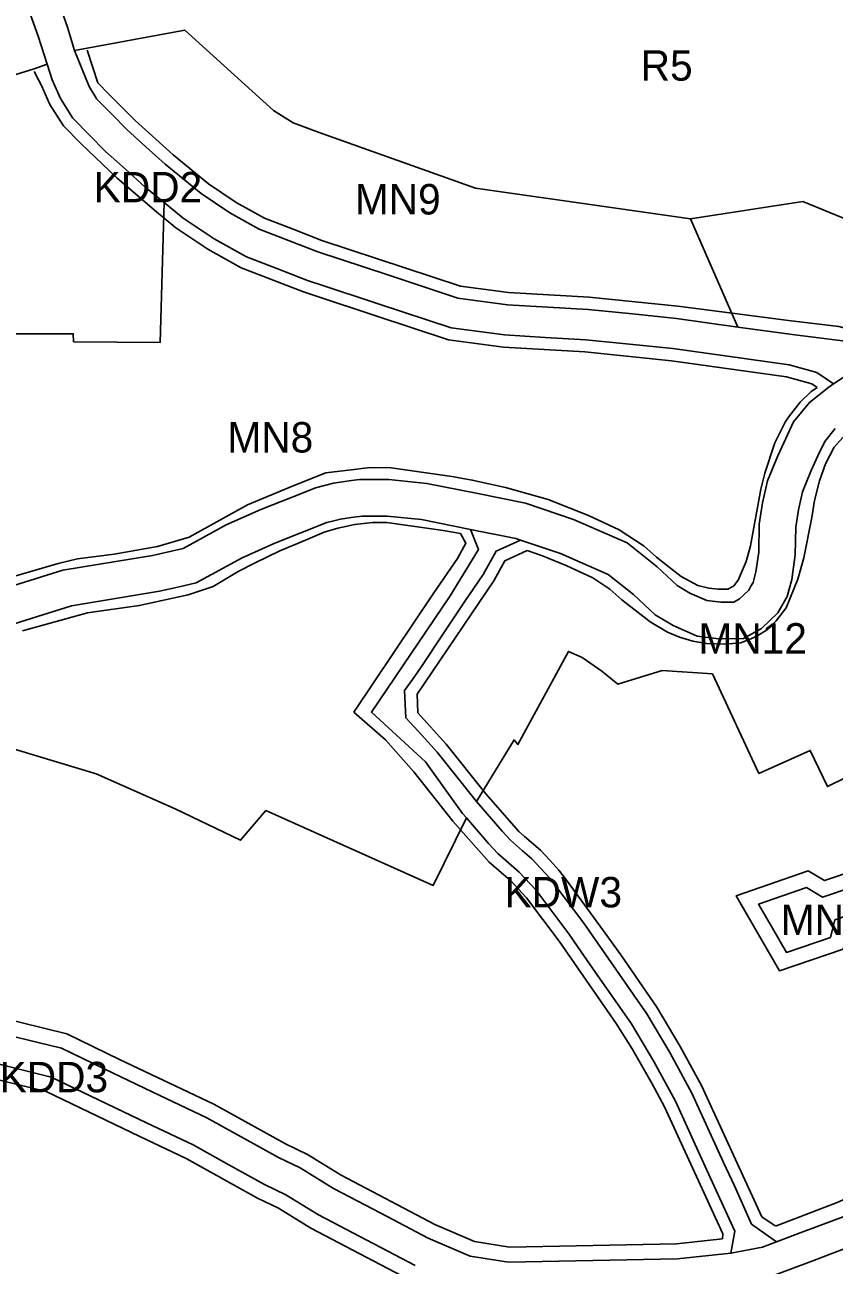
# Model space of a CAD drawing. Extents: x 7428841 to 7433518, y 5545054 to 5546840.
# Drawn here: x 7430056.9 to 7430323, y 5545838 to 5546245.5 of the extents above; entities that cross this region are included whole.
import ezdxf

# ---------------------------------------------------------------- set-up
doc = ezdxf.new("R2010")
doc.units = 0
for name, color, linetype in [('linie_rozgraniczajace', 7, 'Continuous'), ('linie_zabudowy_nieprzekraczalne', 7, 'Continuous'), ('oznaczenia_przeznaczen', 7, 'Continuous')]:
    doc.layers.add(name, color=color, linetype=linetype)

msp = doc.modelspace()

# ---------------------------------------------------------------- linework, layer by layer
at = {"layer": 'linie_rozgraniczajace'}
for points in [[(7430395.71, 5546246.95), (7430410.58, 5546240.65), (7430429.34, 5546232.43), (7430433.09, 5546231.11), (7430441.95, 5546227.01), (7430446.69, 5546224.98), (7430448.57, 5546223.18), (7430461.67, 5546201.97), (7430469.14, 5546186.36), (7430444.59, 5546177.43), (7430426.54, 5546173.53), (7430383.37, 5546165.73), (7430346.89, 5546173.43), (7430312.67, 5546187.52), (7430275.76, 5546181.81), (7430248.12, 5546185.73), (7430205.02, 5546191.83), (7430153.69, 5546210.14), (7430145.11, 5546213.38), (7430138.68, 5546217.35), (7430109.51, 5546243.79), (7430073.19, 5546237.15), (7430070.97, 5546244.81), (7430059.92, 5546275.9)], [(7430059.92, 5546275.9), (7430070.97, 5546244.81), (7430073.19, 5546237.15), (7430078, 5546225.29), (7430080.59, 5546221.14), (7430085.48, 5546216.15), (7430090.37, 5546211.16), (7430096.69, 5546205.48), (7430103.01, 5546199.79), (7430114.86, 5546190.08), (7430124.34, 5546183.79), (7430133.98, 5546178.42), (7430153.22, 5546170.96), (7430176.25, 5546163.35), (7430199.28, 5546155.75), (7430215.56, 5546153.59), (7430228.86, 5546152.81), (7430242.15, 5546152.03), (7430256.64, 5546150.56), (7430271.12, 5546149.09), (7430291.3, 5546146.25), (7430310.03, 5546143.69), (7430332.77, 5546140.78)], [(7430326.24, 5546129.84), (7430322.81, 5546127.56), (7430317.34, 5546131.29), (7430308.14, 5546133.85), (7430287.1, 5546136.77), (7430269.93, 5546139.16), (7430255.64, 5546140.61), (7430241.36, 5546142.06), (7430227.98, 5546142.85), (7430214.61, 5546143.63), (7430197.04, 5546145.96), (7430173.44, 5546153.75), (7430171.43, 5546154.41), (7430155.18, 5546159.78), (7430149.84, 5546161.54), (7430139.78, 5546165.45), (7430129.72, 5546169.35), (7430119.14, 5546175.24), (7430108.91, 5546182.03), (7430102.71, 5546187.11), (7430096.5, 5546192.2), (7430089.97, 5546198.07), (7430083.45, 5546203.94), (7430078.08, 5546209.42), (7430072.71, 5546214.9), (7430068.65, 5546221.3), (7430065.92, 5546227.47), (7430064.19, 5546232.61), (7430061.23, 5546241.83), (7430051.52, 5546269.16)], [(7430027.17, 5546220.98), (7430059.94, 5546231.03), (7430064.19, 5546232.61), (7430065.92, 5546227.47), (7430068.65, 5546221.3), (7430072.71, 5546214.9), (7430078.08, 5546209.42), (7430083.45, 5546203.94), (7430089.97, 5546198.07), (7430096.5, 5546192.2), (7430102.71, 5546187.11), (7430101.41, 5546141.18), (7430072.89, 5546141.43), (7430072.78, 5546144.05), (7430024.7, 5546144.06)], [(7430024.7, 5546144.06), (7430072.78, 5546144.05), (7430072.89, 5546141.43), (7430101.41, 5546141.18), (7430102.71, 5546187.11), (7430108.91, 5546182.03), (7430119.14, 5546175.24), (7430129.72, 5546169.35), (7430139.78, 5546165.45), (7430149.84, 5546161.54), (7430155.18, 5546159.78), (7430171.43, 5546154.41), (7430173.44, 5546153.75), (7430197.04, 5546145.96), (7430214.61, 5546143.63), (7430227.98, 5546142.85), (7430241.36, 5546142.06), (7430255.64, 5546140.61), (7430269.93, 5546139.16), (7430287.1, 5546136.77), (7430308.14, 5546133.85), (7430317.34, 5546131.29), (7430322.81, 5546127.56), (7430321.18, 5546126.47), (7430314.87, 5546121.5), (7430309.65, 5546115.1), (7430304.43, 5546103.89), (7430301.09, 5546095.75), (7430299.44, 5546088.46), (7430298.36, 5546081.51), (7430298.17, 5546072.3), (7430297.26, 5546065.78), (7430296.31, 5546062.32), (7430295.61, 5546061.08), (7430294.91, 5546059.84), (7430293.4, 5546058.41), (7430291.9, 5546056.98), (7430289.96, 5546055.89), (7430287.86, 5546055.85), (7430285.75, 5546055.81), (7430281.12, 5546056.39), (7430275.57, 5546058.82), (7430271.39, 5546061.36), (7430264.81, 5546067.43), (7430254.9, 5546075.34), (7430237.29, 5546083), (7430221.45, 5546088.34), (7430205.28, 5546091.61), (7430189.1, 5546094.88), (7430176.58, 5546096.11), (7430166.97, 5546096.15), (7430164.29, 5546095.77), (7430158.35, 5546094.94), (7430152.48, 5546093.44), (7430148.38, 5546091.82), (7430134.43, 5546086.32), (7430123.03, 5546081.21), (7430108.97, 5546073.51), (7430098.81, 5546071.19), (7430069.41, 5546066.31), (7430038.84, 5546056.81)], [(7430332.77, 5546140.78), (7430310.03, 5546143.69), (7430291.3, 5546146.25), (7430275.76, 5546181.81), (7430312.67, 5546187.52), (7430346.89, 5546173.43)], [(7430108.97, 5546073.51), (7430123.03, 5546081.21), (7430134.43, 5546086.32), (7430148.38, 5546091.82), (7430152.48, 5546093.44), (7430158.35, 5546094.94), (7430164.29, 5546095.77), (7430166.97, 5546096.15), (7430176.58, 5546096.11), (7430189.1, 5546094.88), (7430205.28, 5546091.61), (7430221.45, 5546088.34), (7430237.29, 5546083), (7430254.9, 5546075.34), (7430264.81, 5546067.43), (7430271.39, 5546061.36), (7430275.57, 5546058.82), (7430281.12, 5546056.39), (7430285.75, 5546055.81), (7430287.86, 5546055.85), (7430289.96, 5546055.89), (7430291.9, 5546056.98), (7430293.4, 5546058.41), (7430294.91, 5546059.84), (7430295.61, 5546061.08), (7430296.31, 5546062.32), (7430297.26, 5546065.78), (7430298.17, 5546072.3), (7430298.36, 5546081.51), (7430299.44, 5546088.46), (7430301.09, 5546095.75), (7430304.43, 5546103.89), (7430309.65, 5546115.1), (7430314.87, 5546121.5), (7430321.18, 5546126.47), (7430322.81, 5546127.56), (7430326.24, 5546129.84)], [(7430339.37, 5546004.41), (7430320.75, 5545995.28), (7430315.1, 5546007.13), (7430298.23, 5545999.61), (7430282.96, 5546032.29), (7430266.41, 5546033.35), (7430251.91, 5546028.91), (7430246.58, 5546033.17), (7430240.15, 5546037.7), (7430235.6, 5546039.69), (7430219.01, 5546009.07), (7430217.74, 5546010.62), (7430205.34, 5545990.31), (7430192.42, 5546006.62), (7430187.51, 5546012.03), (7430182.14, 5546017.87), (7430181.77, 5546026.82), (7430184.31, 5546030.45), (7430186.85, 5546034.08), (7430194.64, 5546045.8), (7430201.43, 5546055.91), (7430207.63, 5546064.91), (7430211.84, 5546072.56), (7430219.86, 5546076.21), (7430232.97, 5546071.79), (7430248.66, 5546064.97), (7430256.99, 5546058.32), (7430264.13, 5546051.73), (7430270.02, 5546048.14), (7430277.91, 5546044.7), (7430285.12, 5546043.8), (7430293.2, 5546043.95), (7430299.06, 5546047.24), (7430304.49, 5546052.38), (7430307.48, 5546057.72), (7430309.04, 5546063.33), (7430310.15, 5546071.35), (7430310.34, 5546080.46), (7430311.23, 5546086.21), (7430312.57, 5546092.13), (7430314, 5546095.6), (7430315.42, 5546099.08), (7430317.66, 5546103.88), (7430319.89, 5546108.68), (7430323.33, 5546112.89)], [(7430323.33, 5546112.89), (7430319.89, 5546108.68), (7430317.66, 5546103.88), (7430315.42, 5546099.08), (7430314, 5546095.6), (7430312.57, 5546092.13), (7430311.23, 5546086.21), (7430310.34, 5546080.46), (7430310.15, 5546071.35), (7430309.04, 5546063.33), (7430307.48, 5546057.72), (7430304.49, 5546052.38), (7430299.06, 5546047.24), (7430293.2, 5546043.95), (7430285.12, 5546043.8), (7430277.91, 5546044.7)], [(7430042.04, 5546045.23), (7430072.19, 5546054.6), (7430101.13, 5546059.41), (7430107.2, 5546060.8), (7430113.27, 5546062.18), (7430128.38, 5546070.45), (7430139.09, 5546075.26), (7430147.63, 5546078.63), (7430156.18, 5546082), (7430158.43, 5546082.57), (7430160.67, 5546083.15), (7430164.23, 5546083.64), (7430167.79, 5546084.14), (7430175.97, 5546084.11), (7430187.32, 5546083), (7430202.83, 5546079.86), (7430203.4, 5546079.75), (7430206.03, 5546073.17), (7430196.76, 5546057.94), (7430170.86, 5546019.72), (7430188.61, 5546003.37), (7430200.81, 5545986.39), (7430202.13, 5545985), (7430191.14, 5545962.76), (7430136.15, 5545987.37), (7430127.82, 5545977.63), (7430106.34, 5545987.97), (7430080.36, 5545999.48), (7430047.86, 5546009.17)], [(7430277.91, 5546044.7), (7430270.02, 5546048.14), (7430264.13, 5546051.73), (7430256.99, 5546058.32), (7430248.66, 5546064.97), (7430232.97, 5546071.79), (7430219.86, 5546076.21), (7430218.33, 5546076.73), (7430203.4, 5546079.75), (7430202.83, 5546079.86), (7430187.32, 5546083), (7430175.97, 5546084.11), (7430167.79, 5546084.14), (7430164.23, 5546083.64), (7430160.67, 5546083.15), (7430158.43, 5546082.57), (7430156.18, 5546082), (7430147.63, 5546078.63), (7430139.09, 5546075.26), (7430128.38, 5546070.45), (7430113.27, 5546062.18), (7430107.2, 5546060.8), (7430101.13, 5546059.41), (7430072.19, 5546054.6), (7430042.04, 5546045.23)], [(7429909.72, 5546015.03), (7429921.21, 5546015.41), (7429932.7, 5546015.79), (7429941.42, 5546017.03), (7429954.62, 5546025.5), (7429972.76, 5546035.67), (7429986.76, 5546042.68), (7429993.18, 5546045.73), (7430004.82, 5546048.78), (7430016.01, 5546051.27), (7430038.84, 5546056.81), (7430069.41, 5546066.31), (7430098.81, 5546071.19), (7430108.97, 5546073.51)], [(7430325.91, 5545853.94), (7430312.65, 5545848.93), (7430304.05, 5545845.68), (7430295.86, 5545851.52), (7430290.18, 5545864.11), (7430286.56, 5545871.78), (7430276.15, 5545894.55), (7430268.92, 5545907.86), (7430261.37, 5545920.59), (7430240.64, 5545950.36), (7430234.25, 5545958.91), (7430229.45, 5545965.17), (7430223.6, 5545971.48), (7430220.51, 5545974.18), (7430216.53, 5545977.65), (7430213.79, 5545980.56), (7430205.34, 5545990.31), (7430217.74, 5546010.62), (7430219.01, 5546009.07), (7430235.6, 5546039.69), (7430240.15, 5546037.7), (7430246.58, 5546033.17), (7430251.91, 5546028.91), (7430266.41, 5546033.35), (7430282.96, 5546032.29), (7430298.23, 5545999.61), (7430315.1, 5546007.13), (7430320.75, 5545995.28), (7430339.37, 5546004.41)], [(7430047.86, 5546009.17), (7430080.36, 5545999.48), (7430106.34, 5545987.97), (7430127.82, 5545977.63), (7430136.15, 5545987.37), (7430191.14, 5545962.76), (7430202.13, 5545985), (7430209.33, 5545976.54), (7430212.36, 5545973.32), (7430219.42, 5545967.17), (7430224.86, 5545961.3), (7430235.78, 5545946.85), (7430238.65, 5545942.71), (7430244.53, 5545934.2), (7430256.33, 5545917.33), (7430263.7, 5545904.9), (7430270.78, 5545891.89), (7430281.12, 5545869.27), (7430290.34, 5545849.18), (7430289.06, 5545841.95), (7430271.46, 5545840.08), (7430243.69, 5545839.53), (7430215.92, 5545838.98), (7430203.28, 5545841), (7430189.55, 5545846.91), (7430173.96, 5545855.07), (7430158.36, 5545863.24), (7430147.44, 5545869.97), (7430140.26, 5545873.39), (7430116.76, 5545886.43), (7430101.32, 5545893.77), (7430085.89, 5545901.11), (7430068.96, 5545909.28), (7430046.71, 5545914.73)], [(7430387.48, 5545981.93), (7430319.19, 5545958.9), (7430313.9, 5545962.12), (7430298.13, 5545956.66), (7430302.71, 5545948.72), (7430307.29, 5545940.77), (7430321.76, 5545945.71), (7430323.22, 5545951.5)], [(7430046.71, 5545914.73), (7430068.96, 5545909.28), (7430085.89, 5545901.11), (7430101.32, 5545893.77), (7430116.76, 5545886.43), (7430140.26, 5545873.39), (7430147.44, 5545869.97), (7430158.36, 5545863.24), (7430173.96, 5545855.07), (7430189.55, 5545846.91), (7430203.28, 5545841), (7430215.92, 5545838.98), (7430243.69, 5545839.53), (7430271.46, 5545840.08), (7430289.06, 5545841.95), (7430299.4, 5545843.92), (7430304.05, 5545845.68), (7430312.65, 5545848.93), (7430325.91, 5545853.94)], [(7430185.25, 5545837.88), (7430169.33, 5545846.21), (7430153.41, 5545854.54), (7430142.65, 5545861.18), (7430135.68, 5545864.5), (7430123.93, 5545871.01), (7430112.18, 5545877.53), (7430096.87, 5545884.81), (7430065.56, 5545899.82), (7430045.26, 5545904.79), (7430020.57, 5545906.02), (7429999.63, 5545902.67), (7429977.4, 5545896.7), (7429959.62, 5545892.8), (7429941.85, 5545888.91), (7429925.35, 5545885.29), (7429905.91, 5545878.08)], [(7429905.91, 5545878.08), (7429925.35, 5545885.29), (7429941.85, 5545888.91), (7429959.62, 5545892.8), (7429977.4, 5545896.7), (7429999.63, 5545902.67), (7430020.57, 5545906.02), (7430045.26, 5545904.79), (7430065.56, 5545899.82), (7430096.87, 5545884.81), (7430112.18, 5545877.53), (7430123.93, 5545871.01), (7430135.68, 5545864.5), (7430142.65, 5545861.18), (7430153.41, 5545854.54), (7430169.33, 5545846.21), (7430185.25, 5545837.88)], [(7430329.71, 5545844.69), (7430315.92, 5545839.47), (7430302.12, 5545834.26)], [(7430302.12, 5545834.26), (7430315.92, 5545839.47), (7430329.71, 5545844.69)]]:
    msp.add_lwpolyline(points, dxfattribs=at)
for points in [[(7429949.44, 5546226.76), (7429950.82, 5546228.81), (7429953.67, 5546233.22), (7429972.27, 5546244.79), (7429984.5, 5546249.98), (7430003.93, 5546257.84), (7430047.04, 5546271.67), (7430051.52, 5546269.16), (7430061.23, 5546241.83), (7430064.19, 5546232.61), (7430059.94, 5546231.03), (7430027.17, 5546220.98), (7429994.39, 5546210.92), (7429975.97, 5546200.5), (7429971.21, 5546198.5), (7429967.92, 5546207.41), (7429962.3, 5546218.77), (7429950.2, 5546223.83)], [(7430073.19, 5546237.15), (7430109.51, 5546243.79), (7430138.68, 5546217.35), (7430145.11, 5546213.38), (7430153.69, 5546210.14), (7430205.02, 5546191.83), (7430248.12, 5546185.73), (7430275.76, 5546181.81), (7430291.3, 5546146.25), (7430271.12, 5546149.09), (7430256.64, 5546150.56), (7430242.15, 5546152.03), (7430228.86, 5546152.81), (7430215.56, 5546153.59), (7430199.28, 5546155.75), (7430176.25, 5546163.35), (7430153.22, 5546170.96), (7430133.98, 5546178.42), (7430124.34, 5546183.79), (7430114.86, 5546190.08), (7430103.01, 5546199.79), (7430096.69, 5546205.48), (7430090.37, 5546211.16), (7430085.48, 5546216.15), (7430080.59, 5546221.14), (7430078, 5546225.29)], [(7430170.86, 5546019.72), (7430196.76, 5546057.94), (7430206.03, 5546073.17), (7430203.4, 5546079.75), (7430218.33, 5546076.73), (7430219.86, 5546076.21), (7430211.84, 5546072.56), (7430207.63, 5546064.91), (7430201.43, 5546055.91), (7430194.64, 5546045.8), (7430186.85, 5546034.08), (7430184.31, 5546030.45), (7430181.77, 5546026.82), (7430182.14, 5546017.87), (7430187.51, 5546012.03), (7430192.42, 5546006.62), (7430205.34, 5545990.31), (7430213.79, 5545980.56), (7430216.53, 5545977.65), (7430220.51, 5545974.18), (7430223.6, 5545971.48), (7430229.45, 5545965.17), (7430234.25, 5545958.91), (7430240.64, 5545950.36), (7430261.37, 5545920.59), (7430268.92, 5545907.86), (7430276.15, 5545894.55), (7430286.56, 5545871.78), (7430290.18, 5545864.11), (7430295.86, 5545851.52), (7430304.05, 5545845.68), (7430299.4, 5545843.92), (7430289.06, 5545841.95), (7430290.34, 5545849.18), (7430281.12, 5545869.27), (7430270.78, 5545891.89), (7430263.7, 5545904.9), (7430256.33, 5545917.33), (7430244.53, 5545934.2), (7430238.65, 5545942.71), (7430235.78, 5545946.85), (7430224.86, 5545961.3), (7430219.42, 5545967.17), (7430212.36, 5545973.32), (7430209.33, 5545976.54), (7430202.13, 5545985), (7430200.81, 5545986.39), (7430188.61, 5546003.37)], [(7430298.13, 5545956.66), (7430313.9, 5545962.12), (7430319.19, 5545958.9), (7430387.48, 5545981.93), (7430406.5, 5545994.8), (7430407.64, 5546003.07), (7430419.93, 5545987.45), (7430411.76, 5545988.73), (7430391.08, 5545974.71), (7430357.15, 5545963.1), (7430323.22, 5545951.5), (7430321.76, 5545945.71), (7430307.29, 5545940.77), (7430302.71, 5545948.72)]]:
    msp.add_lwpolyline(points, close=True, dxfattribs=at)
at = {"layer": 'linie_zabudowy_nieprzekraczalne'}
for points in [[(7430077.38, 5546237.2), (7430080.89, 5546226.48), (7430084.68, 5546222.52)], [(7430062.78, 5546224.68), (7430060, 5546230.19)], [(7430152.5, 5546156.47), (7430152.48, 5546156.47), (7430148.49, 5546157.77), (7430128.01, 5546165.72), (7430117.05, 5546171.82), (7430106.54, 5546178.81), (7430100.13, 5546184.05), (7430087.29, 5546195.1), (7430075.27, 5546206.57), (7430069.55, 5546212.4), (7430065.12, 5546219.41), (7430062.81, 5546224.61)], [(7430084.68, 5546222.52), (7430093.14, 5546214.05), (7430105.62, 5546202.82), (7430117.24, 5546193.3), (7430126.42, 5546187.21), (7430135.68, 5546182.05), (7430145.13, 5546178.39), (7430154.57, 5546174.72), (7430200.18, 5546159.67), (7430215.94, 5546157.58), (7430229.21, 5546156.8), (7430242.47, 5546156.02), (7430271.6, 5546153.06), (7430289.42, 5546150.77)], [(7430172.01, 5546149.99), (7430152.48, 5546156.49)], [(7430289.42, 5546150.77), (7430307.96, 5546148.42), (7430324.57, 5546146.39), (7430340.12, 5546142.19), (7430352.42, 5546136.67)], [(7430317.36, 5546126.43), (7430315.63, 5546127.62), (7430307.33, 5546129.93), (7430269.45, 5546135.19), (7430241.04, 5546138.08), (7430214.23, 5546139.65), (7430196.14, 5546142.05), (7430172.01, 5546149.99), (7430172.01, 5546149.99)], [(7430166.02, 5546099.5), (7430167.71, 5546099.8), (7430170.39, 5546100.08), (7430177.35, 5546099.95), (7430197.24, 5546097.16), (7430203.98, 5546095.94), (7430214.91, 5546093.56), (7430228.9, 5546089.59), (7430242.26, 5546084.35), (7430252.34, 5546079.61), (7430260.52, 5546074.21), (7430264.59, 5546070.65), (7430268.71, 5546067.35), (7430272.72, 5546064.24), (7430278.12, 5546061.3), (7430281.73, 5546060.43), (7430284.83, 5546060.14), (7430288.05, 5546060.17), (7430289.68, 5546060.95), (7430289.98, 5546061.25), (7430291.46, 5546063.1), (7430294.03, 5546069.26), (7430295.44, 5546074.37), (7430298.9, 5546092.96), (7430300.22, 5546098.19), (7430303.49, 5546108.15), (7430306.87, 5546115.03), (7430307.95, 5546116.65), (7430311.76, 5546121.54), (7430315.29, 5546124.95), (7430317.36, 5546126.43)], [(7430326.83, 5546111.07), (7430322.98, 5546106.74), (7430320.17, 5546101.29), (7430318.16, 5546095.74), (7430316.52, 5546089.2), (7430315.69, 5546083.62), (7430313.04, 5546070.47), (7430311.07, 5546063.38), (7430307.19, 5546054.03), (7430303.88, 5546049.7), (7430301.07, 5546046.88), (7430297.6, 5546044.63), (7430295.81, 5546043.88), (7430292.28, 5546042.45), (7430289.62, 5546042.24), (7430286.97, 5546042.03), (7430281.16, 5546042.28), (7430276.48, 5546043.05), (7430272.12, 5546044.3), (7430268.22, 5546045.95), (7430262.54, 5546049.36), (7430253.16, 5546056.63), (7430251.2, 5546058.39), (7430249.24, 5546060.15), (7430243.6, 5546063.85), (7430235.08, 5546067.84), (7430227.06, 5546071.09), (7430222, 5546072.86)], [(7430145.09, 5546094.11), (7430155.8, 5546098.34), (7430166.02, 5546099.5)], [(7430007.67, 5546053.2), (7430010.48, 5546052.1), (7430013.34, 5546052.73), (7430040.62, 5546060.65), (7430067.9, 5546068.57), (7430074.2, 5546070.07), (7430086.27, 5546071.65), (7430100.47, 5546074.17), (7430110.9, 5546077.25), (7430130.07, 5546087.79), (7430145.09, 5546094.11)], [(7430200.11, 5546078.43), (7430194.43, 5546079.38), (7430175.92, 5546081.98), (7430171.16, 5546082.07), (7430165.42, 5546081.35), (7430159.81, 5546080.17), (7430155.32, 5546078.82), (7430149.22, 5546076.21), (7430140.72, 5546072.73), (7430132.4, 5546068.71), (7430127.05, 5546065.93), (7430118.76, 5546060.98), (7430110.6, 5546058.28), (7430094.53, 5546054.73), (7430077.46, 5546052.35), (7430056.13, 5546046.46)], [(7430286.27, 5545846.68), (7430286.39, 5545848.37), (7430267.2, 5545890.08), (7430263.2, 5545897.65), (7430256.59, 5545909.05), (7430251.33, 5545917.42), (7430232.53, 5545944.51), (7430221.8, 5545958.72), (7430216.63, 5545964.29), (7430209.59, 5545970.44), (7430197.64, 5545983.93), (7430184.79, 5546000.15), (7430175.5, 5546010.62), (7430165.08, 5546019.75), (7430191.33, 5546058.96), (7430199.11, 5546070.17), (7430201.89, 5546075.23), (7430200.11, 5546078.43)], [(7430222, 5546072.86), (7430214.7, 5546069.47), (7430211.04, 5546062.81), (7430185.83, 5546025.64), (7430186.07, 5546019.5), (7430195.47, 5546009.2), (7430208.42, 5545992.87), (7430219.31, 5545980.53), (7430221.22, 5545978.86), (7430226.39, 5545974.36), (7430229.45, 5545971.06), (7430232.51, 5545967.76), (7430234.98, 5545964.54), (7430246.87, 5545948.3), (7430252.79, 5545940.02), (7430264.73, 5545922.76), (7430272.4, 5545909.84), (7430279.41, 5545897), (7430299.16, 5545853.91), (7430303.63, 5545850.95)], [(7430417.21, 5545982.8), (7430412.93, 5545983.48), (7430393.33, 5545970.19), (7430327.41, 5545947.65), (7430325.95, 5545941.85), (7430305.02, 5545934.71), (7430290.77, 5545959.4), (7430314.49, 5545967.61), (7430319.8, 5545964.38), (7430385.24, 5545986.45), (7430401.85, 5545997.69), (7430402.33, 5546001.78)], [(7430303.75, 5545850.89), (7430324, 5545858.57), (7430341.64, 5545866.42), (7430349.45, 5545871.39), (7430369.83, 5545886.83), (7430383.39, 5545900.53), (7430405.39, 5545922.91), (7430413.84, 5545931.6), (7430417.81, 5545936.52), (7430429.25, 5545957.56), (7430427.65, 5545966.15), (7430424.02, 5545973.98), (7430417.21, 5545982.8)], [(7429901.15, 5545892.32), (7429915.52, 5545897.85), (7429921.4, 5545899.78), (7429956.3, 5545907.43), (7429973.84, 5545911.27), (7429996.49, 5545917.36), (7430019.74, 5545921.08), (7430047.43, 5545919.7), (7430070.66, 5545914.01), (7430088.05, 5545905.62), (7430119.05, 5545890.87), (7430142.55, 5545877.84), (7430149.84, 5545874.37), (7430160.84, 5545867.58), (7430191.7, 5545851.43), (7430204.69, 5545845.83), (7430216.27, 5545843.99), (7430271.14, 5545845.08), (7430286.27, 5545846.68)], [(7430194.95, 5545828.25), (7430183.1, 5545833.36), (7430150.94, 5545850.19), (7430140.26, 5545856.78), (7430133.39, 5545860.05), (7430109.89, 5545873.08), (7430094.72, 5545880.3), (7430063.87, 5545895.09), (7430044.53, 5545899.82), (7430020.84, 5545901), (7430000.68, 5545897.77), (7429978.58, 5545891.84), (7429942.92, 5545884.02), (7429926.67, 5545880.46), (7429922.24, 5545879.01), (7429907.5, 5545873.33)]]:
    msp.add_lwpolyline(points, dxfattribs=at)

# ---------------------------------------------------------------- texts
at = {"layer": 'oznaczenia_przeznaczen'}
for s, p in [('R5', (7430259.37, 5546227.19)), ('KDD2', (7430079.53, 5546187.2)), ('MN9', (7430165.39, 5546183.23)), ('MN8', (7430123.49, 5546105.02)), ('MN12', (7430278.37, 5546038.95)), ('KDW3', (7430214.6, 5545955.57)), ('MN76', (7430305.41, 5545946.5)), ('KDD3', (7430048.6, 5545894.82))]:
    msp.add_text(s, height=10, dxfattribs=at).set_placement(p)

doc.saveas('drawing.dxf')
